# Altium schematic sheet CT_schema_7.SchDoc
size 287 x 160 mm
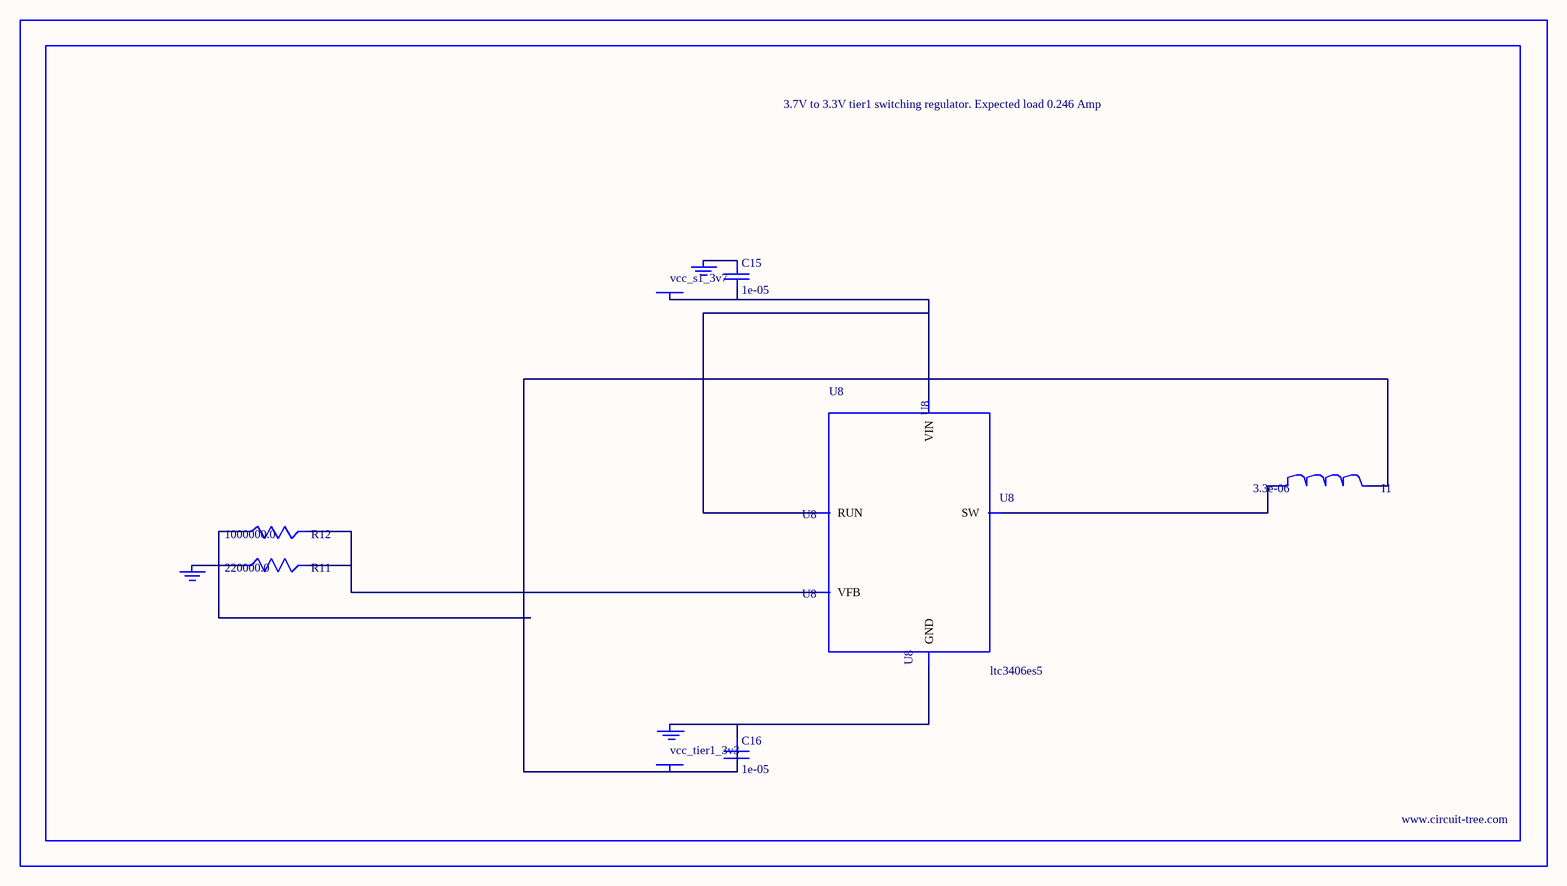
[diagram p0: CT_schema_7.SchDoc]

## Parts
BORDER6  (no value)
C15  1e-05  [C0805]
C16  1e-05  [C0805]
GND_INSTANCE_6_0  (no value)
GND_INSTANCE_6_1  (no value)
GND_INSTANCE_6_2  (no value)
I1  3.3e-06  [L0806]
POWER_INSTANCE_6_0  vcc_tier1_3v3
POWER_INSTANCE_6_1  vcc_s1_3v7
R11  220000.0  [R0603]
R12  1000000.0  [R0603]
U8  ltc3406es5  [TSOT-23-5]

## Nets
NetC15_1: C15.1 GND_INSTANCE_6_1.0(GND)
NetC15_2: C15.2 POWER_INSTANCE_6_1.0(PWR) U8.1(RUN) U8.4(VIN)
NetC16_1: C16.1 GND_INSTANCE_6_0.0(GND) U8.2(GND)
NetC16_2: C16.2 I1.2 POWER_INSTANCE_6_0.0(PWR) R12.1
NetGND_INSTANCE_6_2_0: GND_INSTANCE_6_2.0(GND) R11.1
NetI1_1: I1.1 U8.3(SW)
NetR11_2: R11.2 R12.2 U8.5(VFB)

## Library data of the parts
BORDER6 = BORDER_PAGE6
C15 C16 = C0805C106K8RACTU
GND_INSTANCE_6_0-GND_INSTANCE_6_2 = GND
I1 = L0806C3R3MDWIT
POWER_INSTANCE_6_0 POWER_INSTANCE_6_1 = PWR
R11 = RC0603JR-07220KL
R12 = RC0603JR-071ML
